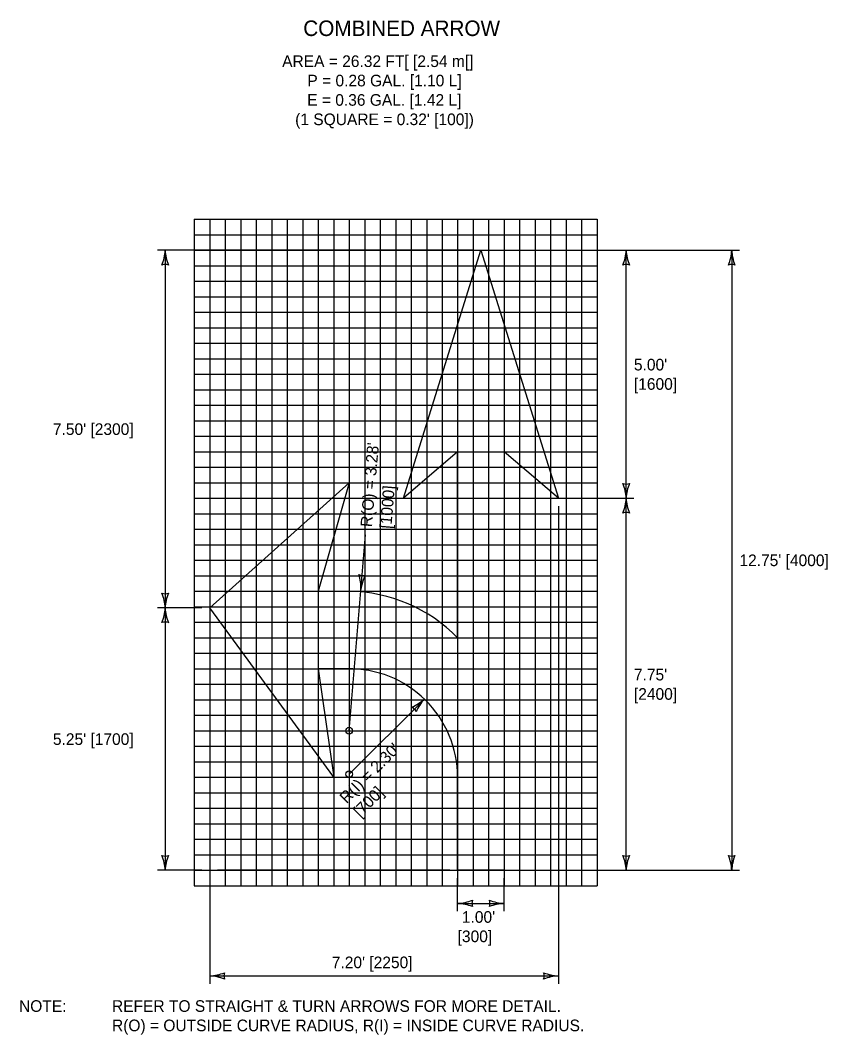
# Model space of a CAD drawing. Extents: x 49991.4 to 50021, y 49980.9 to 50011.4.
# Drawn here: x 50005.62 to 50009.79, y 49980.91 to 49986.14 of the extents above; entities that cross this region are included whole.
import ezdxf

# ---------------------------------------------------------------- set-up
doc = ezdxf.new("R2010")
doc.units = 0
for name, color, linetype in [('Level 1', 7, 'Continuous'), ('Level 2', 7, 'Continuous'), ('Level 3', 7, 'Continuous'), ('Level 9', 7, 'Continuous')]:
    doc.layers.add(name, color=color, linetype=linetype)

msp = doc.modelspace()

# ---------------------------------------------------------------- linework, layer by layer
at = {"layer": 'Level 1'}
for p, q in [((50007.6024, 49983.6747), (50008.0024, 49984.9547)), ((50008.0024, 49984.9547), (50008.4024, 49983.6747)), ((50007.8824, 49983.9147), (50007.6024, 49983.6747)), ((50007.8824, 49982.9547), (50007.8824, 49983.9147)), ((50008.4024, 49983.6747), (50008.1224, 49983.9147)), ((50008.1224, 49983.9147), (50008.1224, 49981.7547)), ((50006.6024, 49983.1088), (50007.3224, 49983.7547)), ((50007.3224, 49983.7547), (50007.1624, 49983.1947)), ((50007.1624, 49983.1947), (50007.3224, 49983.1947)), ((50007.2424, 49982.2347), (50006.6024, 49983.1088)), ((50007.3134, 49982.7947), (50007.1624, 49982.7947)), ((50007.1624, 49982.7947), (50007.2424, 49982.2347)), ((50007.8824, 49981.7547), (50007.8824, 49982.2347)), ((50008.1224, 49981.7547), (50007.8824, 49981.7547))]:
    msp.add_line(p, q, dxfattribs=at)
for centre, radius, start, end in [((50007.311, 49982.3948), 0.8, 44.4189, 89.184), ((50007.3224, 49982.2348), 0.56, 359.9926, 90.9219)]:
    msp.add_arc(centre, radius, start, end, dxfattribs=at)
at = {"layer": 'Level 3'}
for p, q in [((50007.9624, 49984.9547), (50006.3324, 49984.9547)), ((50006.3724, 49984.9547), (50006.3724, 49983.1088)), ((50008.0424, 49984.9547), (50009.3372, 49984.9547)), ((50008.7524, 49983.6747), (50008.7524, 49984.9547)), ((50009.2972, 49984.9547), (50009.2972, 49981.7547)), ((50008.4424, 49983.6747), (50008.7924, 49983.6747)), ((50008.7524, 49981.7547), (50008.7524, 49983.6747)), ((50008.4024, 49983.6347), (50008.4024, 49981.1692)), ((50007.3224, 49982.4747), (50007.4068, 49983.4869)), ((50006.5624, 49983.1088), (50006.3324, 49983.1088)), ((50006.3724, 49983.1088), (50006.3724, 49981.7547)), ((50006.6024, 49983.0688), (50006.6024, 49981.1692)), ((50007.3224, 49982.2507), (50007.7104, 49982.6386)), ((50006.5624, 49981.7547), (50006.3324, 49981.7547)), ((50007.8424, 49981.7547), (50006.6424, 49981.7547)), ((50008.1624, 49981.7547), (50008.3624, 49981.7547)), ((50008.4424, 49981.7547), (50009.3372, 49981.7547)), ((50007.8824, 49981.5437), (50007.8824, 49981.7147)), ((50008.1224, 49981.5437), (50008.1224, 49981.7147)), ((50007.8824, 49981.5837), (50008.1224, 49981.5837)), ((50006.6024, 49981.2092), (50008.4024, 49981.2092))]:
    msp.add_line(p, q, dxfattribs=at)
for centre in [(50007.3224, 49982.4747), (50007.3224, 49982.2507)]:
    msp.add_circle(centre, 0.0175, dxfattribs=at)
for centre, radius, start, end in [((50006.1503, 49984.9638), 0.2223, 337.456, 357.6395), ((50006.6051, 49984.9662), 0.233, 182.8273, 202.0772), ((50008.5303, 49984.9638), 0.2223, 337.456, 357.6395), ((50008.9851, 49984.9662), 0.233, 182.8273, 202.0772), ((50009.0751, 49984.9638), 0.2223, 337.456, 357.6395), ((50009.5299, 49984.9662), 0.233, 182.8273, 202.0772), ((50006.3724, 49984.8265), 0.0548, 72.1388, 107.8612), ((50008.7524, 49984.8265), 0.0548, 72.1388, 107.8612), ((50009.2972, 49984.8265), 0.0548, 72.1388, 107.8612), ((50008.7524, 49983.8029), 0.0548, 252.1388, 287.8612), ((50008.5197, 49983.6632), 0.233, 2.8273, 22.0772), ((50008.9746, 49983.6655), 0.2223, 157.456, 177.6395), ((50008.5303, 49983.6838), 0.2223, 337.456, 357.6395), ((50008.9851, 49983.6862), 0.233, 182.8273, 202.0772), ((50008.7524, 49983.5465), 0.0548, 72.1388, 107.8612), ((50007.3938, 49983.3316), 0.0548, 247.3752, 283.0975), ((50007.1503, 49983.2117), 0.233, 358.0637, 17.3135), ((50007.6038, 49983.1763), 0.2223, 152.6924, 172.8759), ((50006.3724, 49983.237), 0.0548, 252.1388, 287.8612), ((50006.1397, 49983.0973), 0.233, 2.8273, 22.0772), ((50006.5946, 49983.0996), 0.2223, 157.456, 177.6395), ((50006.1503, 49983.118), 0.2223, 337.456, 357.6395), ((50006.6051, 49983.1203), 0.233, 182.8273, 202.0772), ((50006.3724, 49982.9806), 0.0548, 72.1388, 107.8612), ((50007.5598, 49982.8022), 0.2223, 292.456, 312.6395), ((50007.883, 49982.4822), 0.233, 137.8273, 157.0772), ((50007.6197, 49982.548), 0.0548, 27.1388, 62.8612), ((50006.3724, 49981.8829), 0.0548, 252.1388, 287.8612), ((50006.1397, 49981.7432), 0.233, 2.8273, 22.0772), ((50006.5946, 49981.7455), 0.2223, 157.456, 177.6395), ((50008.7524, 49981.8829), 0.0548, 252.1388, 287.8612), ((50008.5197, 49981.7432), 0.233, 2.8273, 22.0772), ((50008.9746, 49981.7455), 0.2223, 157.456, 177.6395), ((50009.2972, 49981.8829), 0.0548, 252.1388, 287.8612), ((50009.0645, 49981.7432), 0.233, 2.8273, 22.0772), ((50009.5194, 49981.7455), 0.2223, 157.456, 177.6395), ((50007.8709, 49981.8164), 0.233, 272.8273, 292.0772), ((50007.8733, 49981.3616), 0.2223, 67.456, 87.6395), ((50008.0106, 49981.5837), 0.0548, 162.1388, 197.8612), ((50008.1316, 49981.8058), 0.2223, 247.456, 267.6395), ((50007.9942, 49981.5837), 0.0548, 342.1388, 17.8612), ((50008.1339, 49981.351), 0.233, 92.8273, 112.0772), ((50006.5909, 49981.4419), 0.233, 272.8273, 292.0772), ((50006.5933, 49980.9871), 0.2223, 67.456, 87.6395), ((50006.7306, 49981.2092), 0.0548, 162.1388, 197.8612), ((50008.4116, 49981.4313), 0.2223, 247.456, 267.6395), ((50008.2742, 49981.2092), 0.0548, 342.1388, 17.8612), ((50008.4139, 49980.9765), 0.233, 92.8273, 112.0772)]:
    msp.add_arc(centre, radius, start, end, dxfattribs=at)
at = {"layer": 'Level 9'}
for p, q in [((50006.5224, 49985.1147), (50006.5224, 49981.6747)), ((50006.5224, 49985.1147), (50008.6024, 49985.1147)), ((50006.6024, 49985.1147), (50006.6024, 49981.6747)), ((50006.6824, 49985.1147), (50006.6824, 49981.6747)), ((50006.7624, 49985.1147), (50006.7624, 49981.6747)), ((50006.8424, 49985.1147), (50006.8424, 49981.6747)), ((50006.9224, 49985.1147), (50006.9224, 49981.6747)), ((50007.0024, 49985.1147), (50007.0024, 49981.6747)), ((50007.0824, 49985.1147), (50007.0824, 49981.6747)), ((50007.1624, 49985.1147), (50007.1624, 49981.6747)), ((50007.2424, 49985.1147), (50007.2424, 49981.6747)), ((50007.3224, 49985.1147), (50007.3224, 49981.6747)), ((50007.4024, 49985.1147), (50007.4024, 49981.6747)), ((50007.4824, 49985.1147), (50007.4824, 49981.6747)), ((50007.5624, 49985.1147), (50007.5624, 49981.6747)), ((50007.6424, 49985.1147), (50007.6424, 49981.6747)), ((50007.7224, 49985.1147), (50007.7224, 49981.6747)), ((50007.8024, 49985.1147), (50007.8024, 49981.6747)), ((50007.8824, 49985.1147), (50007.8824, 49981.6747)), ((50007.9624, 49985.1147), (50007.9624, 49981.6747)), ((50008.0424, 49985.1147), (50008.0424, 49981.6747)), ((50008.1224, 49985.1147), (50008.1224, 49981.6747)), ((50008.2024, 49985.1147), (50008.2024, 49981.6747)), ((50008.2824, 49985.1147), (50008.2824, 49981.6747)), ((50008.3624, 49985.1147), (50008.3624, 49981.6747)), ((50008.4424, 49985.1147), (50008.4424, 49981.6747)), ((50008.5224, 49985.1147), (50008.5224, 49981.6747)), ((50008.6024, 49985.1147), (50008.6024, 49981.6747)), ((50006.5224, 49985.0347), (50008.6024, 49985.0347)), ((50006.5224, 49984.9547), (50008.6024, 49984.9547)), ((50006.5224, 49984.8747), (50008.6024, 49984.8747)), ((50006.5224, 49984.7947), (50008.6024, 49984.7947)), ((50006.5224, 49984.7147), (50008.6024, 49984.7147)), ((50006.5224, 49984.6347), (50008.6024, 49984.6347)), ((50006.5224, 49984.5547), (50008.6024, 49984.5547)), ((50006.5224, 49984.4747), (50008.6024, 49984.4747)), ((50006.5224, 49984.3947), (50008.6024, 49984.3947)), ((50006.5224, 49984.3147), (50008.6024, 49984.3147)), ((50006.5224, 49984.2347), (50008.6024, 49984.2347)), ((50006.5224, 49984.1547), (50008.6024, 49984.1547)), ((50006.5224, 49984.0747), (50008.6024, 49984.0747)), ((50006.5224, 49983.9947), (50008.6024, 49983.9947)), ((50006.5224, 49983.9147), (50008.6024, 49983.9147)), ((50006.5224, 49983.8347), (50008.6024, 49983.8347)), ((50006.5224, 49983.7547), (50008.6024, 49983.7547)), ((50006.5224, 49983.6747), (50008.6024, 49983.6747)), ((50006.5224, 49983.5947), (50008.6024, 49983.5947)), ((50006.5224, 49983.5147), (50008.6024, 49983.5147)), ((50006.5224, 49983.4347), (50008.6024, 49983.4347)), ((50006.5224, 49983.3547), (50008.6024, 49983.3547)), ((50006.5224, 49983.2747), (50008.6024, 49983.2747)), ((50006.5224, 49983.1947), (50008.6024, 49983.1947)), ((50006.5224, 49983.1147), (50008.6024, 49983.1147)), ((50006.5224, 49983.0347), (50008.6024, 49983.0347)), ((50006.5224, 49982.9547), (50008.6024, 49982.9547)), ((50006.5224, 49982.8747), (50008.6024, 49982.8747)), ((50006.5224, 49982.7947), (50008.6024, 49982.7947)), ((50006.5224, 49982.7147), (50008.6024, 49982.7147)), ((50006.5224, 49982.6347), (50008.6024, 49982.6347)), ((50006.5224, 49982.5547), (50008.6024, 49982.5547)), ((50006.5224, 49982.4747), (50008.6024, 49982.4747)), ((50006.5224, 49982.3947), (50008.6024, 49982.3947)), ((50006.5224, 49982.3147), (50008.6024, 49982.3147)), ((50006.5224, 49982.2347), (50008.6024, 49982.2347)), ((50006.5224, 49982.1547), (50008.6024, 49982.1547)), ((50006.5224, 49982.0747), (50008.6024, 49982.0747)), ((50006.5224, 49981.9947), (50008.6024, 49981.9947)), ((50006.5224, 49981.9147), (50008.6024, 49981.9147)), ((50006.5224, 49981.8347), (50008.6024, 49981.8347)), ((50006.5224, 49981.7547), (50008.6024, 49981.7547)), ((50006.5224, 49981.6747), (50008.6024, 49981.6747))]:
    msp.add_line(p, q, dxfattribs=at)

# ---------------------------------------------------------------- texts
at = {"layer": 'Level 2'}
for s, height, p in [('COMBINED ARROW', 0.08, (50007.0852, 49986.0609)), ('AREA = 26.32 FT[ [2.54 m[]', 0.06, (50006.9763, 49985.9009)), ('P = 0.28 GAL. [1.10 L]', 0.06, (50007.1066, 49985.8009)), ('E = 0.36 GAL. [1.42 L]', 0.06, (50007.1055, 49985.7009)), ("(1 SQUARE = 0.32' [100])", 0.06, (50007.0434, 49985.6009)), ("5.00'", 0.06, (50008.7924, 49984.3347)), ('[1600]', 0.06, (50008.7924, 49984.2347)), ("7.50' [2300]", 0.06, (50005.7927, 49984.0017)), ("12.75' [4000]", 0.06, (50009.3372, 49983.3247)), ("7.75'", 0.06, (50008.7924, 49982.7347)), ('[2400]', 0.06, (50008.7924, 49982.6347)), ("5.25' [1700]", 0.06, (50005.7927, 49982.4017)), ("1.00'", 0.06, (50007.9042, 49981.4837)), ('[300]', 0.06, (50007.8822, 49981.3837)), ("7.20' [2250]", 0.06, (50007.2326, 49981.2492)), ('NOTE:', 0.06, (50005.6176, 49981.0239)), ('REFER TO STRAIGHT & TURN ARROWS FOR MORE DETAIL.', 0.06, (50006.0976, 49981.0239)), ('R(O) = OUTSIDE CURVE RADIUS, R(I) = INSIDE CURVE RADIUS.', 0.06, (50006.0976, 49980.9239))]:
    msp.add_text(s, height=height, dxfattribs=at).set_placement(p)
for s, rotation, p in [("R(O) = 3.28'", 85.2364, (50007.44, 49983.5242)), ('[1000]', 85.2364, (50007.5396, 49983.5159)), ("R(I) = 2.30'", 45, (50007.3085, 49982.0953)), ('[700]', 45, (50007.3792, 49982.0246))]:
    msp.add_text(s, height=0.06, rotation=rotation, dxfattribs=at).set_placement(p)

doc.saveas('drawing.dxf')
